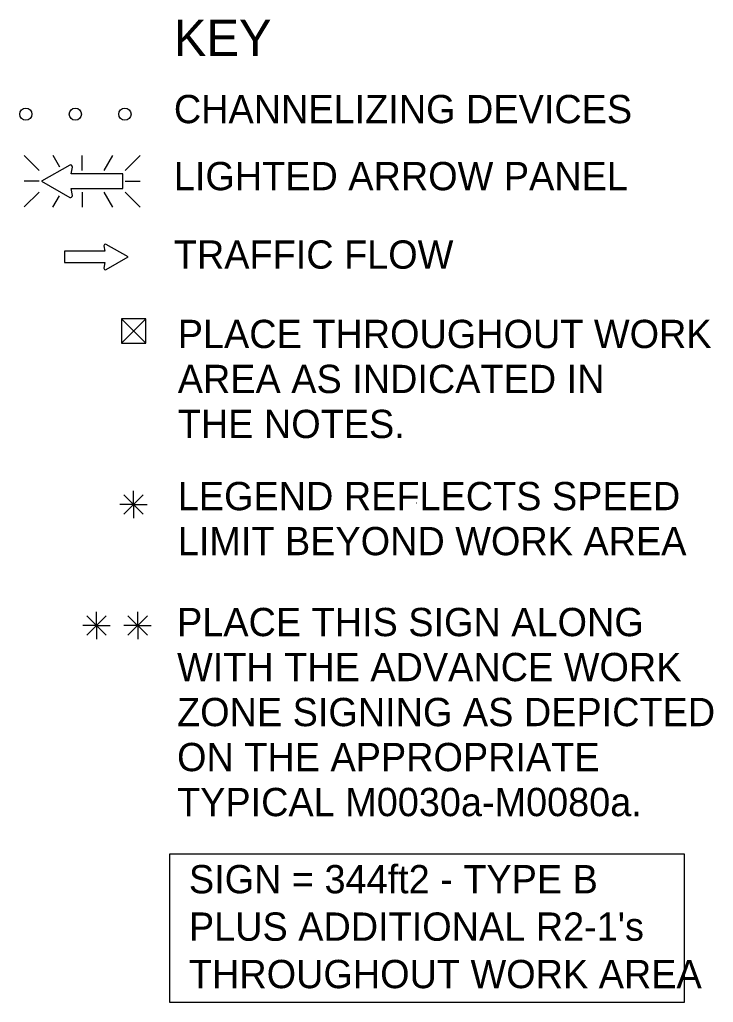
# Model space of a CAD drawing. Extents: x 16728 to 18479, y 5752 to 6927.
# Drawn here: x 17178.3 to 17406.4, y 6585.1 to 6908.3 of the extents above; entities that cross this region are included whole.
import ezdxf

# ---------------------------------------------------------------- set-up
doc = ezdxf.new("R2010")
doc.units = 0
for name, color, linetype in [('MT_SCRATCH_LEVEL_E', 7, 'Continuous'), ('TRAFFIC_SIGNS_PR', 7, 'Continuous'), ('TYPICAL_TEXT_DIMEN_EX', 7, 'Continuous'), ('TYPICAL_TEXT_DIMEN_PR', 7, 'Continuous')]:
    doc.layers.add(name, color=color, linetype=linetype)

msp = doc.modelspace()

# ---------------------------------------------------------------- linework, layer by layer
at = {"layer": 'MT_SCRATCH_LEVEL_E'}
for p, q in [((17206.02, 6833.86), (17206.33, 6832.08)), ((17213.94, 6830.23), (17206.7, 6834.34)), ((17206.33, 6832.08), (17193.08, 6832.08)), ((17193.08, 6832.08), (17193.08, 6828.34)), ((17206.7, 6826.08), (17213.94, 6830.23)), ((17193.08, 6828.34), (17206.33, 6828.34)), ((17206.33, 6828.34), (17206.02, 6826.56))]:
    msp.add_line(p, q, dxfattribs=at)
for centre, start, end in [((17206.48, 6833.93), 60.4248, 189.9638), ((17206.48, 6826.49), 170.0362, 299.7731)]:
    msp.add_arc(centre, 0.463, start, end, dxfattribs=at)
at = {"layer": 'TRAFFIC_SIGNS_PR'}
for p, q in [((17179.75, 6863.61), (17184.69, 6858.68)), ((17191.51, 6859.79), (17189.31, 6863.61)), ((17198.83, 6858.68), (17198.83, 6863.61)), ((17206.07, 6858.68), (17208.92, 6863.61)), ((17212.98, 6858.68), (17217.92, 6863.61)), ((17184.69, 6855.12), (17179.75, 6855.12)), ((17212.98, 6855.12), (17217.92, 6855.12)), ((17179.75, 6846.64), (17184.69, 6851.57)), ((17189.26, 6846.63), (17191.38, 6850.29)), ((17198.83, 6851.57), (17198.83, 6846.63)), ((17208.96, 6846.63), (17206.12, 6851.57)), ((17212.98, 6851.57), (17217.92, 6846.63))]:
    msp.add_line(p, q, dxfattribs=at)
for points in [[(17194.76, 6860.4), (17185.47, 6855.12), (17194.76, 6849.8)], [(17195.64, 6850.43), (17195.24, 6852.7), (17212.25, 6852.7), (17212.25, 6857.5), (17195.24, 6857.5), (17195.64, 6859.78)]]:
    msp.add_lwpolyline(points, dxfattribs=at)
for centre in [(17180.32, 6877.15), (17196.62, 6877.15), (17212.92, 6877.15)]:
    msp.add_circle(centre, 2, dxfattribs=at)
for centre, radius, start, end in [((17195.05, 6859.88), 0.598, 350.7308, 118.8916), ((17195.05, 6850.33), 0.597, 241.4833, 9.9593)]:
    msp.add_arc(centre, radius, start, end, dxfattribs=at)
at = {"layer": 'TYPICAL_TEXT_DIMEN_EX'}
msp.add_lwpolyline([(17227.73, 6633.89), (17396.74, 6633.89), (17396.74, 6585.06), (17227.73, 6585.06)], close=True, dxfattribs=at)
at = {"layer": 'TYPICAL_TEXT_DIMEN_PR'}
for p, q in [((17211.78, 6801.82), (17219.78, 6809.82)), ((17211.79, 6809.82), (17219.78, 6801.82)), ((17212.56, 6751.99), (17218.94, 6745.62)), ((17218.94, 6751.99), (17212.56, 6745.62)), ((17215.75, 6748.81), (17215.75, 6753.26)), ((17215.75, 6748.81), (17211.22, 6748.81)), ((17215.75, 6748.81), (17218.94, 6748.81)), ((17215.75, 6748.81), (17220.22, 6748.81)), ((17215.75, 6748.81), (17215.75, 6744.31)), ((17203.61, 6708.99), (17203.61, 6713.44)), ((17217.11, 6708.99), (17217.11, 6713.44)), ((17200.42, 6712.18), (17206.8, 6705.8)), ((17206.8, 6712.18), (17200.42, 6705.8)), ((17213.93, 6712.18), (17220.3, 6705.8)), ((17220.3, 6712.18), (17213.93, 6705.8)), ((17203.61, 6708.99), (17199.08, 6708.99)), ((17203.61, 6708.99), (17206.8, 6708.99)), ((17203.61, 6708.99), (17208.09, 6708.99)), ((17203.61, 6708.99), (17203.61, 6704.49)), ((17217.11, 6708.99), (17212.58, 6708.99)), ((17217.11, 6708.99), (17220.3, 6708.99)), ((17217.11, 6708.99), (17221.59, 6708.99)), ((17217.11, 6708.99), (17217.11, 6704.49))]:
    msp.add_line(p, q, dxfattribs=at)
msp.add_lwpolyline([(17211.79, 6809.82), (17211.78, 6801.82), (17219.78, 6801.82), (17219.78, 6809.82)], close=True, dxfattribs=at)
msp.add_open_spline([(17308.69, 6749.39), (17308.71, 6749.39), (17308.72, 6749.39), (17308.72, 6749.39)], degree=2, dxfattribs=at)

# ---------------------------------------------------------------- texts
at = {"layer": 'TYPICAL_TEXT_DIMEN_EX'}
for s, height, p in [('KEY', 12, (17229.01, 6896.25)), ('CHANNELIZING DEVICES', 9.3, (17229.01, 6874.2)), ('LIGHTED ARROW PANEL', 9.3, (17229.01, 6852.15)), ('TRAFFIC FLOW', 9.3, (17229.01, 6826.35)), ('PLACE THROUGHOUT WORK', 9.3, (17230.29, 6800.24)), ('AREA AS INDICATED IN', 9.3, (17230.29, 6785.44)), ('THE NOTES.', 9.3, (17230.29, 6770.64)), ('LEGEND REFLECTS SPEED', 9.3, (17230.3, 6746.91)), ('LIMIT BEYOND WORK AREA', 9.3, (17230.3, 6732.11)), ('PLACE THIS SIGN ALONG', 9.3, (17230.06, 6705.49)), ('WITH THE ADVANCE WORK', 9.3, (17230.06, 6690.69)), ('ZONE SIGNING AS DEPICTED', 9.3, (17230.06, 6675.89)), ('ON THE APPROPRIATE', 9.3, (17230.06, 6661.09)), ('TYPICAL M0030a-M0080a.', 9.3, (17230.06, 6646.29)), ('SIGN = 344ft2 - TYPE B', 9.3, (17233.96, 6620.92)), ("PLUS ADDITIONAL R2-1's", 9.3, (17233.96, 6605.32)), ('THROUGHOUT WORK AREA', 9.3, (17233.96, 6589.72))]:
    msp.add_text(s, height=height, dxfattribs=at).set_placement(p)

doc.saveas('drawing.dxf')
